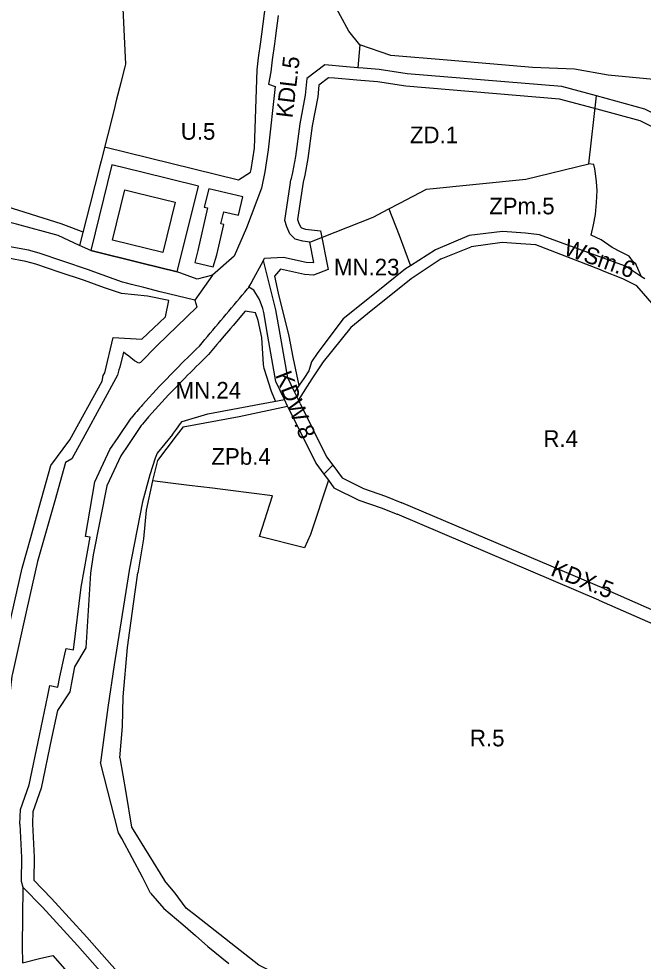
# Model space of a CAD drawing. Extents: x 7431080 to 7433370, y 5546450 to 5548428.
# Drawn here: x 7432003.6 to 7432304.1, y 5547510.7 to 5547964 of the extents above; entities that cross this region are included whole.
import ezdxf

# ---------------------------------------------------------------- set-up
doc = ezdxf.new("R2010")
doc.units = 0
for name, color, linetype in [('Linie Rozgraniczajace', 7, 'Continuous'), ('nieprzekraczalna linia zabudowy', 7, 'Continuous'), ('obowiązująca linia zabudowy', 7, 'Continuous'), ('oznaczenia_przeznaczen', 7, 'Continuous')]:
    doc.layers.add(name, color=color, linetype=linetype)

msp = doc.modelspace()

# ---------------------------------------------------------------- linework, layer by layer
at = {"layer": 'Linie Rozgraniczajace'}
for p, q in [((7432167.68, 5547951.47), (7432166.81, 5547940.45)), ((7432277.9, 5547894.19), (7432281.67, 5547926.87)), ((7432206.86, 5547848.5), (7432221.24, 5547854.22)), ((7432082.61, 5547767.76), (7432079.26, 5547763.36)), ((7432285.14, 5547689.9), (7432187.95, 5547731.21)), ((7432282.75, 5547684.39), (7432185.66, 5547725.66)), ((7432058.77, 5547682.6), (7432060.8, 5547697.5))]:
    msp.add_line(p, q, dxfattribs=at)
for points in [[(7432339.06, 5547911.63), (7432340.97, 5547924.32), (7432341.7, 5547929.78), (7432325.96, 5547930.12), (7432325.9, 5547933.15), (7432287.28, 5547936.86), (7432271.08, 5547939.75), (7432250.79, 5547940.49), (7432209.67, 5547944.14), (7432182.62, 5547946.34), (7432167.68, 5547951.47), (7432162.36, 5547958.11), (7432154.41, 5547972.74), (7432154.32, 5547972.91), (7432151.45, 5547978.19)], [(7432053.44, 5547972.39), (7432054.56, 5547948.74), (7432054.87, 5547942.15), (7432054.56, 5547940.93), (7432053.12, 5547935.2)], [(7432128.41, 5547965.62), (7432127.15, 5547955.74), (7432126.65, 5547951.98), (7432125.58, 5547944.28), (7432124.94, 5547938.42), (7432123.75, 5547932.54), (7432127.02, 5547931.46), (7432123.59, 5547900.92), (7432121.94, 5547890.38), (7432120.42, 5547882.59), (7432113.1, 5547863.48), (7432107.29, 5547849.84), (7432096.81, 5547840.65), (7432088.28, 5547828.62), (7432089.24, 5547825.48), (7432089.3, 5547825.29), (7432070.1, 5547806.76), (7432062.18, 5547798.67), (7432061.4, 5547798.28), (7432059.26, 5547799.51), (7432056.6, 5547801.72), (7432054.93, 5547802.9), (7432053.98, 5547803.57)], [(7432321.65, 5547911.99), (7432304.85, 5547920.53), (7432281.67, 5547926.87), (7432264.9, 5547931.36), (7432190.51, 5547937.49), (7432176.95, 5547939.61), (7432169.32, 5547940.25), (7432166.81, 5547940.45), (7432161.29, 5547940.88), (7432150.9, 5547941.84), (7432142.19, 5547935.29)], [(7432053.12, 5547935.2), (7432052.61, 5547933.16), (7432050.65, 5547925.38), (7432049.24, 5547919.79), (7432046.19, 5547907.71), (7432043.13, 5547895.64), (7432042.52, 5547893.22), (7432037.75, 5547874.42), (7432032.8, 5547854.95)], [(7432142.19, 5547935.29), (7432141.45, 5547927.22), (7432138.82, 5547913.41), (7432136.76, 5547897.78), (7432135.36, 5547890.03), (7432134.53, 5547886.52)], [(7432186.95, 5547875.36), (7432199.8, 5547882.1), (7432247.59, 5547886.83), (7432277.9, 5547894.19)], [(7432303.34, 5547839.8), (7432300.85, 5547845.29), (7432300.48, 5547846.17), (7432299.4, 5547846.9), (7432297.29, 5547849.83), (7432293.24, 5547851.9), (7432289.18, 5547853.96), (7432283.85, 5547857.64), (7432279.01, 5547859.86), (7432280.09, 5547864.86), (7432281.17, 5547869.85), (7432281.55, 5547875.66), (7432281.94, 5547881.47), (7432281.56, 5547885.56), (7432281.18, 5547889.65), (7432280.79, 5547891.75), (7432280.39, 5547893.86), (7432277.9, 5547894.19)], [(7432071.23, 5547787.2), (7432071.54, 5547787.52), (7432072.15, 5547788.14), (7432073.54, 5547789.58), (7432074.93, 5547791.01), (7432076.33, 5547792.45), (7432077.72, 5547793.88), (7432079.12, 5547795.32), (7432080.52, 5547796.74), (7432081.95, 5547798.14), (7432083.37, 5547799.55), (7432084.8, 5547800.95), (7432086.22, 5547802.35), (7432087.65, 5547803.75), (7432089.08, 5547805.15), (7432090.47, 5547806.58), (7432091.76, 5547808.11), (7432093.05, 5547809.64), (7432094.34, 5547811.17), (7432095.64, 5547812.7), (7432096.93, 5547814.22), (7432098.22, 5547815.75), (7432099.51, 5547817.28), (7432100.8, 5547818.81), (7432102.09, 5547820.33), (7432103.38, 5547821.86), (7432104.67, 5547823.39), (7432105.96, 5547824.92), (7432107.25, 5547826.44), (7432108.54, 5547827.97), (7432109.83, 5547829.5), (7432111.12, 5547831.03), (7432112.42, 5547832.56), (7432113.71, 5547834.08), (7432114.27, 5547834.75), (7432114.34, 5547834.87), (7432114.8, 5547835.74), (7432115.49, 5547837.01), (7432115.75, 5547837.5), (7432121.27, 5547847.8), (7432121.85, 5547848.89), (7432130.96, 5547849.31), (7432141.94, 5547846.96), (7432145.61, 5547846.68), (7432143.68, 5547856.53), (7432140.3, 5547856.95), (7432136.5, 5547858.02), (7432134.01, 5547860.5), (7432132.61, 5547863.89), (7432131.61, 5547867.01), (7432134.17, 5547884.14), (7432134.53, 5547886.52)], [(7432143.68, 5547856.53), (7432174.13, 5547868.63), (7432181.74, 5547872.62), (7432186.95, 5547875.36)], [(7432181.74, 5547872.62), (7432186.56, 5547859.92), (7432192.14, 5547845.23)], [(7432096.81, 5547840.65), (7432089.36, 5547838.79), (7432079.86, 5547842.23), (7432062.84, 5547846.43), (7432038.23, 5547852.48), (7432032.8, 5547854.95), (7432022.44, 5547859.67), (7432002.45, 5547865.18), (7431989.08, 5547868.61), (7431987.89, 5547868.79), (7431974.51, 5547869.36), (7431973.55, 5547869.61), (7431968.99, 5547868.62), (7431960.78, 5547865.16)], [(7432247.46, 5547860.8), (7432236.44, 5547861.75), (7432220.36, 5547859.75), (7432204.08, 5547852.91), (7432192.14, 5547845.23), (7432189.73, 5547843.68), (7432174.72, 5547831.69), (7432159.71, 5547819.69), (7432147.5, 5547803.46), (7432144.49, 5547798.97), (7432143.18, 5547794.62)], [(7432286.26, 5547848.3), (7432254.16, 5547860.03), (7432247.46, 5547860.8)], [(7432013.38, 5547851.17), (7432008.2, 5547852.67), (7432003.77, 5547853.46), (7431999.34, 5547854.26), (7431990.32, 5547855.66), (7431981.29, 5547857.06), (7431968.23, 5547854.85), (7431961.43, 5547849.81), (7431958.62, 5547845.75), (7431955.82, 5547841.69), (7431951.79, 5547831.02), (7431947.55, 5547818.1)], [(7432453.95, 5547738.05), (7432450.28, 5547737.86), (7432421.71, 5547753.53), (7432393.13, 5547769.16), (7432369.7, 5547781.35), (7432360.44, 5547787.23), (7432334.74, 5547802.88), (7432323.37, 5547809.83), (7432301.06, 5547835.46), (7432294.22, 5547838.83), (7432284.43, 5547842.82), (7432283.6, 5547843.16), (7432252.46, 5547855.2), (7432245.21, 5547855.78), (7432236.24, 5547856.46), (7432221.24, 5547854.22)], [(7432088.28, 5547828.62), (7432071.56, 5547832.57), (7432063.82, 5547834.74), (7432057.76, 5547836.19), (7432055.47, 5547836.74), (7432053.53, 5547837.32), (7432039.73, 5547842.3), (7432037.04, 5547843.27), (7432024.77, 5547847.38), (7432013.38, 5547851.17)], [(7432138.94, 5547778.96), (7432138.12, 5547780.67), (7432136.3, 5547784.5), (7432133.08, 5547791.3), (7432129.35, 5547812.28), (7432127.35, 5547823.91), (7432121.27, 5547847.8)], [(7432206.86, 5547848.5), (7432192.42, 5547838.95), (7432171.35, 5547822), (7432163.32, 5547815.54)], [(7432303.34, 5547839.8), (7432295.52, 5547844.95), (7432286.26, 5547848.3)], [(7432304.8, 5547838.84), (7432303.34, 5547839.8)], [(7432120.97, 5547824.64), (7432119.39, 5547828.9), (7432116.71, 5547833.41), (7432114.34, 5547834.87)], [(7432133.54, 5547776.33), (7432132.88, 5547777.72), (7432131.41, 5547780.82), (7432127.31, 5547789.46), (7432123.44, 5547811.25), (7432121.48, 5547822.66), (7432120.97, 5547824.64)], [(7432163.32, 5547815.54), (7432150, 5547799.02), (7432144.63, 5547790.73), (7432138.12, 5547780.67)], [(7432053.98, 5547803.57), (7432052.27, 5547796.38), (7432051.66, 5547795.2), (7432051.15, 5547792.5), (7432035.3, 5547763.73), (7432029.04, 5547752.24), (7432026.06, 5547750.51), (7432020.86, 5547732.05)], [(7432143.18, 5547794.62), (7432140.73, 5547791.03), (7432136.3, 5547784.5)], [(7432071.23, 5547787.2), (7432063.09, 5547778.22)], [(7432077.47, 5547763.94), (7432079.46, 5547766.59), (7432081.45, 5547769.25), (7432082.25, 5547770.33), (7432094.52, 5547774.01), (7432131.41, 5547780.82)], [(7432082.61, 5547767.76), (7432109.55, 5547772.74), (7432132.88, 5547777.72)], [(7432138.94, 5547778.96), (7432151.71, 5547753.31), (7432154.71, 5547749.24), (7432159.21, 5547743.14)], [(7432133.54, 5547776.33), (7432146.57, 5547750.17), (7432150.38, 5547745), (7432152.56, 5547742.05), (7432155.24, 5547738.41)], [(7432051.4, 5547762.52), (7432057.65, 5547771.85)], [(7432077.47, 5547763.94), (7432070.13, 5547754.98), (7432069.26, 5547752.56), (7432066.71, 5547744.63), (7432063.07, 5547731.69), (7432056.67, 5547698.79), (7432056.64, 5547698.65)], [(7432079.26, 5547763.36), (7432070.29, 5547751.53), (7432067.88, 5547741.88), (7432067.85, 5547741.76), (7432064.87, 5547727.66), (7432063.58, 5547713.76), (7432060.8, 5547697.5)], [(7432004.09, 5547576.63), (7432004.41, 5547583.6), (7432008.55, 5547595.54), (7432013.49, 5547619.22), (7432017.49, 5547638.41), (7432018.51, 5547643.32), (7432022.43, 5547642.5), (7432023.31, 5547647.49), (7432025.71, 5547658.27), (7432026.34, 5547661.07), (7432029.9, 5547660.42), (7432033.52, 5547690.61), (7432037.98, 5547714.66), (7432035.59, 5547715.02), (7432040.15, 5547741.19), (7432047.45, 5547756.79), (7432051.4, 5547762.52)], [(7432150.38, 5547745), (7432154.71, 5547749.24)], [(7432152.56, 5547742.05), (7432143.95, 5547715.95), (7432141.13, 5547709.57), (7432119.42, 5547715.02), (7432125.72, 5547734.55), (7432105.49, 5547737.07), (7432096.75, 5547738.16), (7432085.49, 5547739.56), (7432076.63, 5547740.67), (7432067.85, 5547741.76)], [(7432159.21, 5547743.14), (7432169.54, 5547738.02), (7432180.06, 5547734.35), (7432187.95, 5547731.21)], [(7432155.24, 5547738.41), (7432167.22, 5547732.48), (7432177.96, 5547728.73), (7432185.66, 5547725.66)], [(7432020.86, 5547732.05), (7432016.75, 5547717.49), (7432012.64, 5547702.92), (7432007.51, 5547680.17), (7432000.51, 5547649.08), (7432000.49, 5547648.98), (7432000.2, 5547647.72), (7431999.57, 5547642.18), (7431997.56, 5547624.45), (7431992.07, 5547593.98), (7431991.57, 5547589.71), (7431990.28, 5547578.67), (7431990.26, 5547576.43), (7431989.92, 5547534.61), (7431989.83, 5547504.09)], [(7432056.64, 5547698.65), (7432049.52, 5547653.28), (7432046.44, 5547632.64), (7432042.95, 5547606.23)], [(7432285.14, 5547689.9), (7432310.89, 5547678.5), (7432324.8, 5547673.63), (7432338.1, 5547669.08), (7432352.28, 5547664.36), (7432371.54, 5547658.93), (7432382.65, 5547656.27), (7432391.14, 5547652.61), (7432392.71, 5547651.93), (7432409.48, 5547644.73), (7432428.05, 5547637.22), (7432446.52, 5547629.24), (7432464.7, 5547620.99), (7432482.96, 5547612.86)], [(7432053.41, 5547623.53), (7432053.83, 5547637.84), (7432055.81, 5547661.51), (7432058.77, 5547682.6)], [(7432282.75, 5547684.39), (7432308.69, 5547672.92), (7432322.84, 5547667.97), (7432336.18, 5547663.4), (7432350.52, 5547658.62), (7432370.02, 5547653.13), (7432380.75, 5547650.55), (7432388.76, 5547647.09), (7432390.35, 5547646.41), (7432407.04, 5547639.25), (7432407.18, 5547639.19), (7432425.73, 5547631.68), (7432444.05, 5547623.78), (7432462.24, 5547615.51), (7432480.52, 5547607.38)], [(7432052.17, 5547608.42), (7432053.41, 5547623.53)], [(7432067.03, 5547543.45), (7432063.11, 5547551.07), (7432053.13, 5547569.64), (7432051.56, 5547572.41), (7432042.95, 5547606.23)], [(7432052.17, 5547608.42), (7432055.01, 5547591.79), (7432057.85, 5547575.15), (7432058.57, 5547573.89), (7432066.13, 5547561.64), (7432073.69, 5547549.39)], [(7432004.09, 5547576.63), (7432004.92, 5547560.57), (7432004.73, 5547549.15), (7432005.55, 5547546.28)], [(7432005.55, 5547546.28), (7432005.23, 5547517.84), (7432005.39, 5547509.93), (7432013.55, 5547511.88), (7432019.96, 5547513.41), (7432031.57, 5547500.29), (7432055.49, 5547472.7)], [(7432005.55, 5547546.28), (7432014.94, 5547536.67), (7432031.83, 5547518.22), (7432043.81, 5547504.57), (7432051.97, 5547495.61), (7432058.36, 5547488.24), (7432064.88, 5547480.17)], [(7432321.38, 5547487.39), (7432288.19, 5547494.38), (7432271.81, 5547495.5), (7432264.27, 5547495.78), (7432247.98, 5547490.91), (7432214.17, 5547486.01), (7432197.88, 5547486.15), (7432192.94, 5547487), (7432151.81, 5547494.19), (7432136.9, 5547498.95), (7432122.92, 5547506.87), (7432119.08, 5547508.81), (7432089.1, 5547532.34), (7432084.17, 5547536.1), (7432078.89, 5547543.36), (7432073.69, 5547549.39)], [(7432067.03, 5547543.45), (7432073.4, 5547536.04), (7432082.54, 5547528.28), (7432088.55, 5547522.96), (7432094.52, 5547517.65), (7432104.67, 5547509.61)]]:
    msp.add_lwpolyline(points, dxfattribs=at)
msp.add_arc((7432169.76, 5547681.56), 143.95, 137.8221, 141.1556, dxfattribs=at)
at = {"layer": 'nieprzekraczalna linia zabudowy'}
msp.add_line((7432152.4, 5547843.32), (7432145.42, 5547840.67), dxfattribs=at)
for points in [[(7431564.48, 5548151.97), (7431671.34, 5547988.63), (7431935.33, 5547892.09), (7431953.85, 5547887.49), (7432023.85, 5547865.52)], [(7432109.33, 5547886.55), (7432115.14, 5547890.27), (7432115.37, 5547891.45), (7432117, 5547901.83), (7432118.36, 5547939.41), (7432118.98, 5547945.15), (7432120.06, 5547952.9), (7432120.56, 5547956.63), (7432121.82, 5547966.54), (7432123.02, 5547974.76), (7432122.93, 5547975.75), (7432124.57, 5547994.27), (7432125.09, 5548006.27), (7432125.39, 5548018.12), (7432125.29, 5548020.31), (7432125.02, 5548035.43), (7432124.65, 5548047.67), (7432124.72, 5548051.57), (7432124.91, 5548062.28), (7432124.87, 5548063.42)], [(7432317.86, 5547907.18), (7432302.67, 5547914.89), (7432280.1, 5547921.06), (7432263.86, 5547925.41), (7432189.8, 5547931.52), (7432176.24, 5547933.64), (7432166.31, 5547934.45), (7432155.56, 5547935.37), (7432152.66, 5547935.64), (7432147.93, 5547932.09), (7432147.41, 5547926.38), (7432144.76, 5547912.45), (7432142.71, 5547896.85), (7432141.24, 5547888.8), (7432140.44, 5547885.38), (7432140.12, 5547883.24), (7432137.76, 5547867.51), (7432138.26, 5547865.96), (7432139.11, 5547863.91), (7432139.64, 5547863.38), (7432141.49, 5547862.86), (7432148.74, 5547861.96), (7432152.4, 5547843.32)], [(7432044.83, 5547902.35), (7432109.33, 5547886.55)], [(7432023.85, 5547865.52), (7432028.96, 5547863.61), (7432034.46, 5547861.5)], [(7432075.73, 5547828.54), (7432075.73, 5547828.54), (7432065.53, 5547830.55), (7432052.93, 5547831.77), (7432044.78, 5547834.64), (7432035.24, 5547838.09), (7432023.03, 5547842.18), (7432011.75, 5547845.93), (7432006.95, 5547847.32), (7431998.43, 5547848.85)], [(7432129.46, 5547843.49), (7432126.65, 5547840.15)], [(7432145.42, 5547840.67), (7432141.08, 5547841), (7432129.46, 5547843.49)], [(7432126.65, 5547840.15), (7432128.45, 5547832.05), (7432133.53, 5547811.34), (7432135.48, 5547801.27), (7432138.4, 5547787.59)], [(7432048.93, 5547810.61), (7432048.93, 5547810.61), (7432048.93, 5547810.61), (7432048.93, 5547810.61), (7432062.81, 5547809.83), (7432074.15, 5547820.55), (7432075.73, 5547828.54)], [(7432117.49, 5547822.53), (7432112.52, 5547823.4), (7432106.67, 5547816.46), (7432105.38, 5547814.94), (7432101.51, 5547810.35), (7432100.21, 5547808.82), (7432098.92, 5547807.29), (7432094.92, 5547802.55), (7432093.33, 5547800.91), (7432090.42, 5547798.07), (7432089, 5547796.67), (7432087.58, 5547795.28), (7432086.16, 5547793.87), (7432084.76, 5547792.49), (7432083.41, 5547791.12), (7432082.02, 5547789.7), (7432080.63, 5547788.27), (7432079.23, 5547786.83), (7432077.85, 5547785.41), (7432076.45, 5547783.95), (7432075.83, 5547783.33), (7432075.61, 5547783.1), (7432067.56, 5547774.21), (7432066, 5547772.46), (7432064.5, 5547770.73), (7432063.03, 5547768.96), (7432062.48, 5547768.28), (7432056.36, 5547759.15), (7432052.67, 5547753.8), (7432045.94, 5547739.4), (7432039.28, 5547706.1), (7432038.07, 5547697.35), (7432035.77, 5547661.33), (7432030.32, 5547652.26)], [(7432127.18, 5547780.04), (7432125.24, 5547784.72), (7432121.61, 5547795.77), (7432121.27, 5547797.73), (7432120.53, 5547810.65), (7432118.83, 5547818.93), (7432117.49, 5547822.53)], [(7431994.54, 5547652.62), (7432000.02, 5547676.93), (7432005.17, 5547699.78), (7432009.31, 5547714.46), (7432013.42, 5547729.01), (7432019.06, 5547749.03), (7432028.2, 5547761.53), (7432043.75, 5547789.75), (7432044.25, 5547792.4), (7432044.9, 5547793.66), (7432048.93, 5547810.61)], [(7432030.32, 5547652.26), (7432029.2, 5547646.35), (7432028.13, 5547640.28), (7432022.14, 5547631.32)], [(7432022.14, 5547631.32), (7432019.36, 5547618), (7432014.34, 5547593.94), (7432010.36, 5547582.46), (7432010.1, 5547576.65), (7432010.92, 5547560.68), (7432010.74, 5547549.56)], [(7432010.74, 5547549.56), (7432019.3, 5547540.79), (7432036.3, 5547522.23), (7432048.28, 5547508.57), (7432056.46, 5547499.6), (7432062.96, 5547492.09), (7432069.14, 5547484.44), (7432078.02, 5547477.31), (7432085.41, 5547472.26), (7432102.24, 5547459.68), (7432127.99, 5547444.79), (7432146.19, 5547441.93), (7432156.95, 5547440.23), (7432167.21, 5547439.02), (7432177.48, 5547437.79), (7432201.99, 5547435.74), (7432209.91, 5547435.07), (7432225.82, 5547433.22), (7432231.1, 5547432.54), (7432235.81, 5547431.94), (7432250.04, 5547430.44), (7432264.27, 5547428.92), (7432273.56, 5547428.15), (7432276.13, 5547427.93)]]:
    msp.add_lwpolyline(points, dxfattribs=at)
at = {"layer": 'obowiązująca linia zabudowy'}
for points in [[(7432062.77, 5547890.19), (7432048.36, 5547893.73), (7432038.23, 5547852.48), (7432062.84, 5547846.43), (7432079.86, 5547842.23), (7432089.99, 5547883.54), (7432062.77, 5547890.19)], [(7432078.82, 5547875.78), (7432072.85, 5547851.6), (7432048.65, 5547857.58), (7432054.63, 5547881.78)], [(7432054.62, 5547881.75), (7432060.34, 5547880.34), (7432078.82, 5547875.78)]]:
    msp.add_lwpolyline(points, dxfattribs=at)
msp.add_lwpolyline([(7432094.98, 5547882.19), (7432092.8, 5547873.43), (7432094.4, 5547873.06), (7432089.68, 5547852.6), (7432088.23, 5547846.74), (7432097.19, 5547844.6), (7432098.84, 5547850.45), (7432102.22, 5547865.08), (7432100.84, 5547865.4), (7432102.18, 5547871.17), (7432109.37, 5547869.51), (7432111.42, 5547878.4)], close=True, dxfattribs=at)

# ---------------------------------------------------------------- texts
at = {"layer": 'oznaczenia_przeznaczen'}
for s, rotation, p in [('KDL.5', 83.0629, (7432135.27, 5547915.98)), ('WSm.6', 340.5903, (7432265.25, 5547850.72)), ('KDW.8', 291.3165, (7432126.88, 5547792.64)), ('KDX.5', 338.1906, (7432259.05, 5547696.39))]:
    msp.add_text(s, height=8, rotation=rotation, dxfattribs=at).set_placement(p)
for s, p in [('U.5', (7432081.52, 5547905.82)), ('ZD.1', (7432191.81, 5547904.13)), ('ZPm.5', (7432229.94, 5547869.93)), ('MN.23', (7432155.27, 5547840.57)), ('MN.24', (7432079.04, 5547781.31)), ('R.4', (7432256.05, 5547758.08)), ('ZPb.4', (7432096.26, 5547749.46)), ('R.5', (7432220.69, 5547614))]:
    msp.add_text(s, height=8, dxfattribs=at).set_placement(p)

doc.saveas('drawing.dxf')
